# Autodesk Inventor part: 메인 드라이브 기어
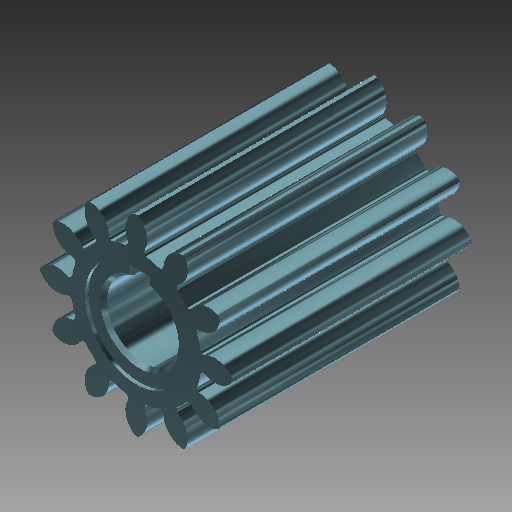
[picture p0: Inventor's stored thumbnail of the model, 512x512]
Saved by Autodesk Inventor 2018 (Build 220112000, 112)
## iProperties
Created: 2013-07
Part Number: 메인 드라이브 기어
Document SubType Name: Modeling
Designer: 한국산업디자인학원
Density: 1 g/cm^3
Mass: 93.0555 g
Surface Area: 295.478 cm^2
Volume: 93.0555 cm^3
Material: 강철, 탄소
Appearance: 반광택(1)
변환 표준: STEP AP214IS
파일 이름: C:\Documents and Settings\?댁씪諛곗?1\諛뷀깢 ?붾㈃\2013-07-27 ?덉긽臾몄젣\媛?몄삩 援ъ꽦?붿냼\留ㅺ컻蹂??MZ)?섏젙?섎㈃ ?먮룞? 留뚮뱾?댁????ㅽ띁湲곗뼱.stp
전처리기: Build: 223b, Release: 2010 RTM - Date: Sat 02/14/2009
전송 단위: 밀리미터
불확실성: 0.01
Author: 한국산업디자인학원
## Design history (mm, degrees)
sketch "스케치1"
  geometry: A1 r 6 centre (-2.816, 23.011) between (2.462, 20.157) and (0.524, 27.995) reference; A2 r 28 centre (0, 0) between (0.524, 27.995) and (-0.524, 27.995) reference; A3 r 6 centre (2.816, 23.011) between (-0.524, 27.995) and (-2.462, 20.157) reference; A4 r 0.972 centre (-3.318, 19.695) between (-3.156, 18.736) and (-2.462, 20.157) reference; A5 r 19 centre (0, 0) between (-3.156, 18.736) and (-6.635, 17.804) reference; A6 r 0.972 centre (-6.974, 18.715) between (-7.946, 18.688) and (-6.635, 17.804) reference; A7 r 6 centre (-13.944, 18.52) between (-7.946, 18.688) and (-13.544, 24.506) reference; A8 r 28 centre (0, 0) between (-13.544, 24.506) and (-14.451, 23.983) reference; A9 r 6 centre (-9.067, 21.336) between (-14.451, 23.983) and (-12.211, 16.226) reference; A10 r 0.972 centre (-12.721, 15.397) between (-12.101, 14.648) and (-12.211, 16.226) reference; A11 r 19 centre (0, 0) between (-12.101, 14.648) and (-14.648, 12.101) reference; A12 r 0.972 centre (-15.397, 12.721) between (-16.226, 12.211) and (-14.648, 12.101) reference; A13 r 6 centre (-21.336, 9.067) between (-16.226, 12.211) and (-23.983, 14.451) reference; A14 r 28 centre (0, 0) between (-23.983, 14.451) and (-24.506, 13.544) reference; A15 r 6 centre (-18.52, 13.944) between (-24.506, 13.544) and (-18.688, 7.946) reference; A16 r 0.972 centre (-18.715, 6.974) between (-17.804, 6.635) and (-18.688, 7.946) reference; A17 r 19 centre (0, 0) between (-17.804, 6.635) and (-18.736, 3.156) reference; A18 r 0.972 centre (-19.695, 3.318) between (-20.157, 2.462) and (-18.736, 3.156) reference; A19 r 6 centre (-23.011, -2.816) between (-20.157, 2.462) and (-27.995, 0.524) reference; A20 r 28 centre (0, 0) between (-27.995, 0.524) and (-27.995, -0.524) reference; A21 r 6 centre (-23.011, 2.816) between (-27.995, -0.524) and (-20.157, -2.462) reference; A22 r 0.972 centre (-19.695, -3.318) between (-18.736, -3.156) and (-20.157, -2.462) reference; A23 r 19 centre (0, 0) between (-18.736, -3.156) and (-17.804, -6.635) reference; A24 r 0.972 centre (-18.715, -6.974) between (-18.688, -7.946) and (-17.804, -6.635) reference; A25 r 6 centre (-18.52, -13.944) between (-18.688, -7.946) and (-24.506, -13.544) reference; A26 r 28 centre (0, 0) between (-24.506, -13.544) and (-23.983, -14.451) reference; A27 r 6 centre (-21.336, -9.067) between (-23.983, -14.451) and (-16.226, -12.211) reference; A28 r 0.972 centre (-15.397, -12.721) between (-14.648, -12.101) and (-16.226, -12.211) reference; A29 r 19 centre (0, 0) between (-14.648, -12.101) and (-12.101, -14.648) reference; A30 r 0.972 centre (-12.721, -15.397) between (-12.211, -16.226) and (-12.101, -14.648) reference; A31 r 6 centre (-9.067, -21.336) between (-12.211, -16.226) and (-14.451, -23.983) reference; A32 r 28 centre (0, 0) between (-14.451, -23.983) and (-13.544, -24.506) reference; A33 r 6 centre (-13.944, -18.52) between (-13.544, -24.506) and (-7.946, -18.688) reference; A34 r 0.972 centre (-6.974, -18.715) between (-6.635, -17.804) and (-7.946, -18.688) reference; A35 r 19 centre (0, 0) between (-6.635, -17.804) and (-3.156, -18.736) reference; A36 r 0.972 centre (-3.318, -19.695) between (-2.462, -20.157) and (-3.156, -18.736) reference; A37 r 6 centre (2.816, -23.011) between (-2.462, -20.157) and (-0.524, -27.995) reference; A38 r 28 centre (0, 0) between (-0.524, -27.995) and (0.524, -27.995) reference; A39 r 6 centre (-2.816, -23.011) between (0.524, -27.995) and (2.462, -20.157) reference; A40 r 0.972 centre (3.318, -19.695) between (3.156, -18.736) and (2.462, -20.157) reference; A41 r 19 centre (0, 0) between (3.156, -18.736) and (6.635, -17.804) reference; A42 r 0.972 centre (6.974, -18.715) between (7.946, -18.688) and (6.635, -17.804) reference; A43 r 6 centre (13.944, -18.52) between (7.946, -18.688) and (13.544, -24.506) reference; A44 r 28 centre (0, 0) between (13.544, -24.506) and (14.451, -23.983) reference; A45 r 6 centre (9.067, -21.336) between (14.451, -23.983) and (12.211, -16.226) reference; A46 r 0.972 centre (12.721, -15.397) between (12.101, -14.648) and (12.211, -16.226) reference; A47 r 19 centre (0, 0) between (12.101, -14.648) and (14.648, -12.101) reference; A48 r 0.972 centre (15.397, -12.721) between (16.226, -12.211) and (14.648, -12.101) reference; A49 r 6 centre (21.336, -9.067) between (16.226, -12.211) and (23.983, -14.451) reference; A50 r 28 centre (0, 0) between (23.983, -14.451) and (24.506, -13.544) reference; A51 r 6 centre (18.52, -13.944) between (24.506, -13.544) and (18.688, -7.946) reference; A52 r 0.972 centre (18.715, -6.974) between (17.804, -6.635) and (18.688, -7.946) reference; A53 r 19 centre (0, 0) between (17.804, -6.635) and (18.736, -3.156) reference; A54 r 0.972 centre (19.695, -3.318) between (20.157, -2.462) and (18.736, -3.156) reference; A55 r 6 centre (23.011, 2.816) between (20.157, -2.462) and (27.995, -0.524) reference; A56 r 28 centre (0, 0) between (27.995, -0.524) and (27.995, 0.524) reference; A57 r 6 centre (23.011, -2.816) between (27.995, 0.524) and (20.157, 2.462) reference; A58 r 0.972 centre (19.695, 3.318) between (18.736, 3.156) and (20.157, 2.462) reference; A59 r 19 centre (0, 0) between (18.736, 3.156) and (17.804, 6.635) reference; A60 r 0.972 centre (18.715, 6.974) between (18.688, 7.946) and (17.804, 6.635) reference; A61 r 6 centre (18.52, 13.944) between (18.688, 7.946) and (24.506, 13.544) reference; A62 r 28 centre (0, 0) between (24.506, 13.544) and (23.983, 14.451) reference; A63 r 6 centre (21.336, 9.067) between (23.983, 14.451) and (16.226, 12.211) reference; A64 r 0.972 centre (15.397, 12.721) between (14.648, 12.101) and (16.226, 12.211) reference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; 1 further point
extrude "돌출1" new body sketch "스케치1" stored distance "d0" = 70; taper "d1" = 0 deg
sketch "스케치2"
  geometry: L1 (-3, 10.062)-(-3, 13.3); L2 (-3, 13.3)-(3, 13.3); L3 (3, 13.3)-(3, 10.062); A1 r 10.5 centre (0, 0) between (-3, 10.062) and (3, 10.062); 1 further point
  constraints: 6 end point, 2 parallel, 2 point on circle, 1 centre point, 1 coincident, 1 perpendicular, 1 vertical
  dimensions: "d2" = 21 diameter of A1; "d3" = 6 distance of L1.end L2.end; "d4" = 23.8 dimension on A1 L2 (computed from d2)
extrude "돌출2" cut sketch "스케치2" extent not by distance; stored distance "d5" = 10; taper "d6" = 0 deg
sketch "스케치3"
  geometry: C1 r 14 at (0, 0) reference; C2 r 15 at (0, 0); 1 further point
  constraints: 1 centre point
  dimensions: "d10" = 1 radial gap between concentric circles of C2 C1
extrude "돌출3" cut sketch "스케치3" distance "d11" = 1; taper "d12" = 0 deg
chamfer "모따기2" distance "d13" = 1; stored, may be unused: second distance "d14" = 2, angle "d15" = 45 deg
node "솔리드4"
mirror "대칭1"
node "투영된 루프1"
node "솔리드2"
node "참조1"
